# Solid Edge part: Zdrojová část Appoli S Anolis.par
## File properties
Title: Zdrojová část Appoli S Anolis
Author: petr.kostka
Keywords: ---
Template: Part Robe 03_24.par
Last saved by: petr.kostka
Revision: 37
Application: Solid Edge
Company: 19030931-01M
Hustota: 2680,000 kg/m^3
Přesnost: 0,990
Username: petr.kostka
Typ obsahu dokumentu: 0
Material: LM6 - slitina hliníku
Face Style: Model Default
Fill Style: Normal
Virtual Style: Normal
Skupiny: Slitiny hliníku
LibraryName: Robe knihovna - Konstrukce
Coef. of Thermal Exp: 0.0
Thermal Conductivity: 0.0
Specific Heat: 0.0
Modulus of Elasticity: 0.0
Poisson's Ratio: 0.0
Yield Stress: 0.0
Ultimate Stress: 0.0
Elongation: 0.0
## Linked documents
st Appoli S Anolis.par
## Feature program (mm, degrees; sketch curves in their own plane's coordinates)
part copy "KopírovanáSoučást_1"
delete faces "unnamed DeleteFaces 1"
delete regions assoc c "unnamed DeleteRegionsAssocC 1"
delete faces "unnamed DeleteFaces 2"
delete blends "unnamed DeleteBlends 1"
delete faces "unnamed DeleteFaces 3"
delete faces "unnamed DeleteFaces 4"
delete faces "unnamed DeleteFaces 5"
delete faces "unnamed DeleteFaces 6"
delete faces "unnamed DeleteFaces 7"
delete faces "unnamed DeleteFaces 8"
delete faces "unnamed DeleteFaces 9"
delete faces "unnamed DeleteFaces 10"
sketch for "Vysunutí_2" plane through (0, 29.597, 39.7974) normal (0, -0.999391, -0.034899) x-axis (-1, 0, 0)
  line (0, 0) -> (0, 0)
  line (0, 0) -> (0, 0)
  line (-22.4286, -2.0922) -> (23.2828, -2.0922)
  line (23.2828, -2.0922) -> (23.2828, -8.8183)
  line (23.2828, -8.8183) -> (-22.4286, -8.8183)
  line (-22.4286, -8.8183) -> (-22.4286, -2.0922)
extrude "Vysunutí_2" add finite 1 along +normal
delete faces "unnamed DeleteFaces 11"
delete faces "unnamed DeleteFaces 12"
delete faces "unnamed DeleteFaces 13"
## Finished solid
Body 1: solid body, 519 faces, 1060 edges, 543 vertices.
  Faces by surface: blend 194, sphere 92, cylinder 75, swept 50, plane 46, spline 28, torus 14, cone 12, spun 8
  Edges by curve: intersection 384, circle 346, line 164, curve on surface 158, ellipse 8
Bounding box of the edges (mm; curved faces can reach further): 121.175 x 66.700 x 121.492, from (-60.5877, 0, -60.746) to (60.5877, 66.7, 60.7463).
Cylindrical faces by radius (mm): R0.5 x70, R2 x3, R6 x2
Conical faces (half-angle, radius in mm at the cone's reference point): 1.0959 deg R14.5272 x4, 1.0974 deg R14.5525 x4, 3 deg R5.5 x4
Toroidal faces (ring radius, tube radius in mm): R5.2628 r0.25 x4, R6.1303 r0.25 x4, R6.5 r0.5 x2, R15.0906 r0.5 x4
Spherical faces by radius (mm): R0.5 x92
Planar faces by outward normal: +y 17, +z 1, -y 1, oblique 27
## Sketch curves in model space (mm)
line (-23.2829, 29.5239, 41.8884) -> (-23.2829, 29.2892, 48.6104)
line (-23.2829, 29.2892, 48.6104) -> (22.4286, 29.2892, 48.6104)
line (22.4286, 29.2892, 48.6104) -> (22.4286, 29.5239, 41.8884)
line (22.4286, 29.5239, 41.8884) -> (-23.2829, 29.5239, 41.8884)
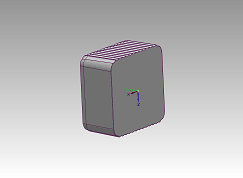
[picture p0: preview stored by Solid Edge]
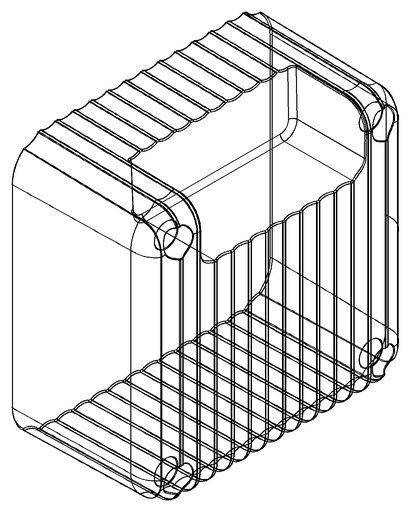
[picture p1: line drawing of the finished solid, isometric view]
